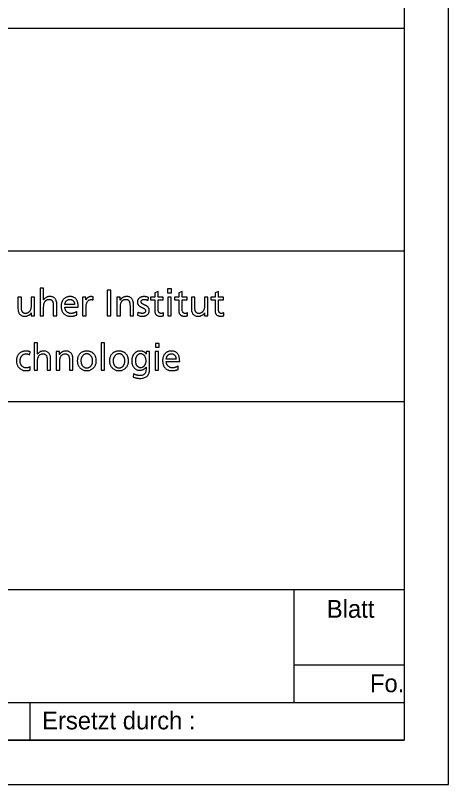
# Model space of a CAD drawing. Extents: x 0 to 420, y 0 to 297.
# Drawn here: x 396.16 to 420.5, y 0 to 43.24 of the extents above; entities that cross this region are included whole.
import ezdxf

# ---------------------------------------------------------------- set-up
doc = ezdxf.new("R2010")
doc.units = 0
doc.layers.add('90_Plankopf', color=7, linetype='Continuous')

msp = doc.modelspace()

# ---------------------------------------------------------------- linework, layer by layer
at = {"layer": '90_Plankopf'}
for p, q in [((418, 42.495), (329.06, 42.495)), ((418, 42.495), (418, 2.5)), ((329.06, 29.995), (418, 29.995)), ((329.06, 29.995), (418, 29.995)), ((418, 29.995), (418, 2.5)), ((400.528, 27.242), (400.528, 27.416)), ((403.616, 27.22), (403.633, 27.389)), ((399.486, 26.98), (398.941, 26.98)), ((398.941, 26.836), (399.693, 26.836)), ((399.612, 26.396), (399.612, 26.59)), ((403.036, 26.559), (403.026, 26.386)), ((404.481, 26.357), (404.481, 26.522)), ((405.833, 26.357), (405.833, 26.522)), ((407.872, 26.357), (407.872, 26.522)), ((396.976, 24.168), (396.992, 24.329)), ((405.186, 23.92), (404.642, 23.92)), ((397, 23.312), (396.986, 23.485)), ((404.642, 23.776), (405.393, 23.776)), ((405.312, 23.337), (405.312, 23.53)), ((402.798, 23.087), (402.777, 22.907)), ((376.001, 21.535), (418, 21.535)), ((376.001, 10.96), (418, 10.96)), ((411.824, 4.615), (411.824, 10.96)), ((411.824, 6.73), (418, 6.73)), ((376.001, 4.615), (418, 4.615)), ((397.001, 2.5), (397.001, 4.615)), ((418, 2.5), (329.06, 2.5)), ((334.9, 2.5), (418, 2.5)), ((334.9, 2.5), (418, 2.5))]:
    msp.add_line(p, q, dxfattribs=at)
for points in [[(0, 0), (420.5, 0), (420.5, 297), (0, 297)], [(12.5, 294.5), (418, 294.5), (418, 2.5), (12.5, 2.5)]]:
    msp.add_lwpolyline(points, close=True, dxfattribs=at)
for points in [[(397.755, 27.255), (397.751, 27.255), (397.751, 27.9), (397.557, 27.9), (397.557, 26.353), (397.751, 26.353), (397.751, 26.84)], [(401.323, 26.353), (401.529, 26.353), (401.529, 27.793), (401.323, 27.793), (401.323, 26.353)], [(404.186, 26.673), (404.186, 27.248), (404.464, 27.248), (404.464, 27.405), (404.186, 27.405), (404.186, 27.711), (403.992, 27.649), (403.992, 27.405), (403.754, 27.405), (403.754, 27.248), (403.992, 27.248), (403.992, 26.633)], [(404.927, 27.64), (404.927, 27.859), (404.708, 27.859), (404.708, 27.64), (404.927, 27.64)], [(405.538, 26.673), (405.538, 27.248), (405.816, 27.248), (405.816, 27.405), (405.538, 27.405), (405.538, 27.711), (405.344, 27.649), (405.344, 27.405), (405.106, 27.405), (405.106, 27.248), (405.344, 27.248), (405.344, 26.633)], [(407.577, 26.673), (407.577, 27.248), (407.855, 27.248), (407.855, 27.405), (407.577, 27.405), (407.577, 27.711), (407.383, 27.649), (407.383, 27.405), (407.146, 27.405), (407.146, 27.248), (407.383, 27.248), (407.383, 26.633)], [(396.502, 26.86), (396.502, 27.405), (396.308, 27.405), (396.308, 26.78)], [(397.047, 26.52), (397.051, 26.52), (397.051, 26.353), (397.239, 26.353), (397.239, 27.405), (397.045, 27.405), (397.045, 26.918)], [(400.126, 27.242), (400.122, 27.242), (400.122, 27.405), (399.94, 27.405), (399.94, 26.353), (400.134, 26.353), (400.134, 26.832)], [(402.058, 27.238), (402.054, 27.238), (402.054, 27.405), (401.866, 27.405), (401.866, 26.353), (402.06, 26.353), (402.06, 26.84)], [(404.72, 27.405), (404.72, 26.353), (404.914, 26.353), (404.914, 27.405), (404.72, 27.405)], [(406.242, 26.86), (406.242, 27.405), (406.048, 27.405), (406.048, 26.78)], [(406.786, 26.52), (406.79, 26.52), (406.79, 26.353), (406.978, 26.353), (406.978, 27.405), (406.784, 27.405), (406.784, 26.918)], [(398.293, 26.898), (398.293, 26.353), (398.487, 26.353), (398.487, 26.978)], [(402.603, 26.898), (402.603, 26.353), (402.797, 26.353), (402.797, 26.978)], [(397.409, 24.195), (397.405, 24.195), (397.405, 24.841), (397.211, 24.841), (397.211, 23.293), (397.405, 23.293), (397.405, 23.78)], [(400.982, 23.293), (401.176, 23.293), (401.176, 24.841), (400.982, 24.841), (400.982, 23.293)], [(404.247, 24.581), (404.247, 24.799), (404.028, 24.799), (404.028, 24.581), (404.247, 24.581)], [(398.652, 24.178), (398.647, 24.178), (398.647, 24.346), (398.46, 24.346), (398.46, 23.293), (398.654, 23.293), (398.654, 23.78)], [(403.698, 23.339), (403.698, 24.346), (403.518, 24.346), (403.518, 24.189), (403.514, 24.189)], [(404.015, 24.346), (404.015, 23.293), (404.209, 23.293), (404.209, 24.346), (404.015, 24.346)], [(397.948, 23.838), (397.948, 23.293), (398.142, 23.293), (398.142, 23.918)], [(399.196, 23.838), (399.196, 23.293), (399.39, 23.293), (399.39, 23.918)], [(403.5, 23.456), (403.504, 23.456), (403.504, 23.353)]]:
    msp.add_lwpolyline(points, dxfattribs=at)
for points in [[(397.751, 26.84), (397.751, 26.904), (397.757, 26.963), (397.77, 27.016), (397.782, 27.069), (397.802, 27.114), (397.828, 27.152), (397.854, 27.191), (397.887, 27.221), (397.927, 27.242), (397.968, 27.262), (398.015, 27.273), (398.071, 27.273), (398.127, 27.27), (398.171, 27.254), (398.204, 27.226), (398.236, 27.198), (398.259, 27.156), (398.273, 27.102), (398.287, 27.048), (398.294, 26.979), (398.293, 26.898)], [(398.487, 26.978), (398.488, 27.073), (398.474, 27.154), (398.446, 27.221), (398.418, 27.288), (398.374, 27.34), (398.316, 27.376), (398.258, 27.412), (398.184, 27.43), (398.093, 27.43), (398.019, 27.43), (397.954, 27.414), (397.895, 27.384), (397.837, 27.354), (397.791, 27.311), (397.755, 27.255)], [(399.693, 26.836), (399.693, 26.921), (399.685, 26.999), (399.67, 27.071), (399.654, 27.143), (399.628, 27.206), (399.592, 27.26), (399.556, 27.313), (399.509, 27.355), (399.449, 27.385), (399.389, 27.414), (399.316, 27.43), (399.228, 27.43), (399.154, 27.43), (399.086, 27.416), (399.026, 27.391), (398.966, 27.365), (398.914, 27.328), (398.87, 27.281), (398.827, 27.233), (398.794, 27.177), (398.771, 27.112), (398.747, 27.048), (398.736, 26.976), (398.735, 26.898), (398.735, 26.812), (398.746, 26.734), (398.768, 26.664), (398.789, 26.594), (398.823, 26.534), (398.868, 26.485), (398.912, 26.434), (398.969, 26.396), (399.037, 26.369), (399.106, 26.342), (399.187, 26.328), (399.28, 26.328), (399.337, 26.328), (399.386, 26.332), (399.427, 26.34), (399.467, 26.347), (399.502, 26.356), (399.532, 26.367), (399.561, 26.377), (399.588, 26.387), (399.612, 26.396)], [(398.941, 26.98), (398.945, 27.015), (398.953, 27.049), (398.965, 27.083), (398.977, 27.118), (398.994, 27.149), (399.017, 27.178), (399.04, 27.206), (399.068, 27.229), (399.102, 27.247), (399.136, 27.264), (399.177, 27.273), (399.224, 27.273), (399.266, 27.273), (399.303, 27.265), (399.336, 27.25), (399.368, 27.235), (399.395, 27.214), (399.418, 27.187), (399.44, 27.16), (399.457, 27.129), (399.469, 27.094), (399.48, 27.059), (399.486, 27.021), (399.486, 26.98)], [(400.528, 27.416), (400.515, 27.418), (400.502, 27.421), (400.49, 27.423), (400.478, 27.425), (400.464, 27.427), (400.45, 27.428), (400.436, 27.429), (400.419, 27.43), (400.401, 27.43), (400.363, 27.43), (400.327, 27.422), (400.291, 27.406), (400.256, 27.39), (400.224, 27.368), (400.196, 27.339), (400.167, 27.311), (400.144, 27.279), (400.126, 27.242)], [(400.134, 26.832), (400.135, 26.92), (400.147, 26.996), (400.17, 27.06), (400.194, 27.124), (400.227, 27.174), (400.27, 27.208), (400.312, 27.243), (400.363, 27.26), (400.421, 27.261), (400.438, 27.261), (400.456, 27.26), (400.474, 27.257), (400.493, 27.254), (400.511, 27.249), (400.528, 27.242)], [(402.797, 26.978), (402.797, 27.073), (402.783, 27.154), (402.755, 27.221), (402.727, 27.288), (402.684, 27.34), (402.626, 27.376), (402.568, 27.412), (402.493, 27.43), (402.402, 27.43), (402.353, 27.43), (402.306, 27.422), (402.261, 27.407), (402.216, 27.392), (402.176, 27.37), (402.14, 27.341), (402.105, 27.312), (402.077, 27.278), (402.058, 27.238)], [(402.06, 26.84), (402.06, 26.904), (402.066, 26.963), (402.079, 27.016), (402.092, 27.069), (402.111, 27.114), (402.137, 27.152), (402.163, 27.191), (402.196, 27.221), (402.237, 27.242), (402.277, 27.262), (402.325, 27.273), (402.38, 27.273), (402.436, 27.27), (402.48, 27.254), (402.513, 27.226), (402.546, 27.198), (402.569, 27.156), (402.582, 27.102), (402.597, 27.048), (402.603, 26.979), (402.603, 26.898)], [(403.633, 27.389), (403.595, 27.4), (403.556, 27.41), (403.517, 27.418), (403.478, 27.426), (403.436, 27.43), (403.391, 27.43), (403.339, 27.43), (403.29, 27.423), (403.245, 27.41), (403.2, 27.397), (403.161, 27.377), (403.127, 27.35), (403.094, 27.323), (403.067, 27.29), (403.049, 27.249), (403.03, 27.208), (403.02, 27.161), (403.02, 27.106), (403.02, 27.064), (403.029, 27.028), (403.045, 26.997), (403.061, 26.966), (403.083, 26.94), (403.11, 26.917), (403.137, 26.895), (403.167, 26.875), (403.199, 26.857), (403.232, 26.84), (403.264, 26.824), (403.296, 26.809), (403.329, 26.793), (403.358, 26.777), (403.385, 26.761), (403.412, 26.745), (403.434, 26.727), (403.451, 26.706), (403.467, 26.686), (403.475, 26.663), (403.476, 26.636), (403.475, 26.607), (403.469, 26.584), (403.457, 26.564), (403.445, 26.545), (403.43, 26.529), (403.41, 26.518), (403.39, 26.506), (403.369, 26.498), (403.346, 26.493), (403.323, 26.487), (403.3, 26.485), (403.278, 26.485), (403.258, 26.485), (403.235, 26.488), (403.207, 26.493), (403.179, 26.499), (403.15, 26.507), (403.12, 26.518), (403.09, 26.529), (403.062, 26.543), (403.036, 26.559)], [(403.026, 26.386), (403.071, 26.363), (403.117, 26.347), (403.167, 26.339), (403.215, 26.331), (403.265, 26.327), (403.315, 26.328), (403.362, 26.328), (403.408, 26.335), (403.451, 26.348), (403.495, 26.361), (403.534, 26.381), (403.569, 26.408), (403.603, 26.435), (403.631, 26.469), (403.651, 26.51), (403.671, 26.551), (403.682, 26.6), (403.682, 26.656), (403.682, 26.704), (403.673, 26.745), (403.657, 26.778), (403.64, 26.811), (403.619, 26.84), (403.592, 26.863), (403.565, 26.886), (403.535, 26.906), (403.503, 26.922), (403.47, 26.939), (403.438, 26.954), (403.406, 26.968), (403.373, 26.983), (403.343, 26.998), (403.317, 27.013), (403.289, 27.029), (403.268, 27.047), (403.251, 27.068), (403.235, 27.089), (403.226, 27.115), (403.226, 27.145), (403.226, 27.174), (403.235, 27.198), (403.252, 27.217), (403.269, 27.236), (403.292, 27.25), (403.32, 27.259), (403.347, 27.269), (403.378, 27.273), (403.412, 27.273), (403.423, 27.273), (403.439, 27.271), (403.457, 27.269), (403.475, 27.266), (403.494, 27.261), (403.515, 27.256), (403.535, 27.251), (403.554, 27.246), (403.572, 27.239), (403.59, 27.233), (403.605, 27.226), (403.616, 27.22)], [(397.045, 26.918), (397.045, 26.854), (397.039, 26.795), (397.026, 26.742), (397.013, 26.69), (396.994, 26.644), (396.968, 26.606), (396.941, 26.567), (396.908, 26.538), (396.868, 26.517), (396.828, 26.496), (396.78, 26.485), (396.725, 26.485), (396.669, 26.488), (396.624, 26.504), (396.592, 26.532), (396.559, 26.561), (396.536, 26.602), (396.522, 26.656), (396.508, 26.71), (396.502, 26.779), (396.502, 26.86)], [(399.612, 26.59), (399.6, 26.58), (399.583, 26.569), (399.559, 26.557), (399.536, 26.545), (399.51, 26.534), (399.48, 26.523), (399.45, 26.512), (399.419, 26.503), (399.386, 26.496), (399.353, 26.489), (399.32, 26.485), (399.288, 26.485), (399.242, 26.485), (399.198, 26.493), (399.156, 26.51), (399.115, 26.527), (399.078, 26.551), (399.046, 26.582), (399.014, 26.613), (398.988, 26.65), (398.97, 26.693), (398.951, 26.736), (398.942, 26.783), (398.941, 26.836)], [(406.784, 26.918), (406.784, 26.854), (406.778, 26.795), (406.765, 26.742), (406.753, 26.69), (406.733, 26.644), (406.707, 26.606), (406.681, 26.567), (406.648, 26.538), (406.607, 26.517), (406.567, 26.496), (406.519, 26.485), (406.464, 26.485), (406.408, 26.488), (406.364, 26.504), (406.331, 26.532), (406.299, 26.561), (406.276, 26.602), (406.262, 26.656), (406.248, 26.71), (406.241, 26.779), (406.242, 26.86)], [(396.308, 26.78), (396.308, 26.685), (396.322, 26.605), (396.35, 26.537), (396.378, 26.47), (396.421, 26.418), (396.479, 26.382), (396.537, 26.347), (396.612, 26.328), (396.702, 26.328), (396.751, 26.328), (396.799, 26.336), (396.844, 26.351), (396.889, 26.367), (396.929, 26.389), (396.964, 26.417), (397, 26.446), (397.027, 26.48), (397.047, 26.52)], [(403.992, 26.633), (403.992, 26.563), (404.005, 26.506), (404.031, 26.461), (404.057, 26.416), (404.095, 26.382), (404.143, 26.36), (404.191, 26.339), (404.249, 26.328), (404.316, 26.328), (404.347, 26.328), (404.377, 26.332), (404.405, 26.338), (404.434, 26.344), (404.459, 26.35), (404.481, 26.357)], [(404.481, 26.522), (404.466, 26.513), (404.448, 26.504), (404.426, 26.497), (404.404, 26.489), (404.379, 26.485), (404.349, 26.485), (404.319, 26.485), (404.292, 26.492), (404.267, 26.507), (404.243, 26.521), (404.223, 26.542), (404.208, 26.57), (404.194, 26.598), (404.186, 26.632), (404.186, 26.673)], [(405.344, 26.633), (405.344, 26.563), (405.357, 26.506), (405.383, 26.461), (405.409, 26.416), (405.447, 26.382), (405.495, 26.36), (405.543, 26.339), (405.601, 26.328), (405.668, 26.328), (405.699, 26.328), (405.729, 26.332), (405.757, 26.338), (405.786, 26.344), (405.811, 26.35), (405.833, 26.357)], [(405.833, 26.522), (405.818, 26.513), (405.8, 26.504), (405.778, 26.497), (405.756, 26.489), (405.731, 26.485), (405.701, 26.485), (405.671, 26.485), (405.644, 26.492), (405.619, 26.507), (405.595, 26.521), (405.575, 26.542), (405.56, 26.57), (405.546, 26.598), (405.538, 26.632), (405.538, 26.673)], [(406.048, 26.78), (406.048, 26.685), (406.061, 26.605), (406.089, 26.537), (406.117, 26.47), (406.16, 26.418), (406.219, 26.382), (406.277, 26.347), (406.351, 26.328), (406.442, 26.328), (406.491, 26.328), (406.538, 26.336), (406.583, 26.351), (406.628, 26.367), (406.669, 26.389), (406.704, 26.417), (406.739, 26.446), (406.767, 26.48), (406.786, 26.52)], [(407.383, 26.633), (407.383, 26.563), (407.396, 26.506), (407.422, 26.461), (407.449, 26.416), (407.486, 26.382), (407.534, 26.36), (407.582, 26.339), (407.64, 26.328), (407.707, 26.328), (407.738, 26.328), (407.768, 26.332), (407.796, 26.338), (407.825, 26.344), (407.85, 26.35), (407.872, 26.357)], [(407.872, 26.522), (407.857, 26.513), (407.839, 26.504), (407.818, 26.497), (407.796, 26.489), (407.77, 26.485), (407.74, 26.485), (407.71, 26.485), (407.683, 26.492), (407.658, 26.507), (407.634, 26.521), (407.614, 26.542), (407.6, 26.57), (407.585, 26.598), (407.577, 26.632), (407.577, 26.673)], [(396.992, 24.329), (396.973, 24.337), (396.951, 24.343), (396.924, 24.35), (396.897, 24.356), (396.869, 24.361), (396.84, 24.365), (396.811, 24.368), (396.783, 24.37), (396.757, 24.37), (396.676, 24.37), (396.603, 24.356), (396.537, 24.329), (396.472, 24.302), (396.415, 24.264), (396.368, 24.215), (396.321, 24.166), (396.284, 24.108), (396.259, 24.041), (396.234, 23.973), (396.221, 23.9), (396.22, 23.819), (396.221, 23.744), (396.234, 23.673), (396.26, 23.606), (396.285, 23.54), (396.322, 23.482), (396.37, 23.431), (396.417, 23.381), (396.474, 23.341), (396.539, 23.312), (396.605, 23.284), (396.677, 23.269), (396.757, 23.268), (396.781, 23.268), (396.806, 23.269), (396.833, 23.272), (396.861, 23.274), (396.889, 23.278), (396.917, 23.284), (396.946, 23.29), (396.973, 23.299), (397, 23.312)], [(396.986, 23.485), (396.966, 23.472), (396.944, 23.461), (396.92, 23.452), (396.896, 23.443), (396.872, 23.437), (396.848, 23.432), (396.823, 23.428), (396.8, 23.425), (396.777, 23.425), (396.728, 23.426), (396.684, 23.433), (396.645, 23.448), (396.607, 23.463), (396.574, 23.484), (396.546, 23.51), (396.518, 23.536), (396.496, 23.566), (396.478, 23.6), (396.461, 23.633), (396.448, 23.669), (396.439, 23.706), (396.431, 23.744), (396.427, 23.782), (396.427, 23.819), (396.427, 23.87), (396.434, 23.919), (396.449, 23.965), (396.464, 24.012), (396.486, 24.054), (396.515, 24.091), (396.544, 24.129), (396.579, 24.158), (396.621, 24.18), (396.663, 24.202), (396.711, 24.213), (396.765, 24.213), (396.797, 24.213), (396.83, 24.21), (396.866, 24.202), (396.902, 24.195), (396.938, 24.184), (396.976, 24.168)], [(397.405, 23.78), (397.405, 23.845), (397.411, 23.903), (397.424, 23.956), (397.437, 24.009), (397.456, 24.054), (397.482, 24.093), (397.508, 24.131), (397.542, 24.161), (397.582, 24.182), (397.622, 24.203), (397.67, 24.213), (397.725, 24.213), (397.781, 24.21), (397.825, 24.195), (397.858, 24.166), (397.891, 24.138), (397.914, 24.097), (397.928, 24.042), (397.942, 23.988), (397.948, 23.92), (397.948, 23.838)], [(398.142, 23.918), (398.142, 24.013), (398.128, 24.094), (398.1, 24.161), (398.072, 24.229), (398.029, 24.28), (397.971, 24.316), (397.913, 24.352), (397.838, 24.37), (397.748, 24.37), (397.674, 24.37), (397.608, 24.355), (397.55, 24.325), (397.492, 24.294), (397.445, 24.251), (397.409, 24.195)], [(399.39, 23.918), (399.391, 24.013), (399.377, 24.094), (399.349, 24.161), (399.321, 24.229), (399.277, 24.28), (399.219, 24.316), (399.161, 24.352), (399.087, 24.37), (398.996, 24.37), (398.947, 24.37), (398.9, 24.362), (398.855, 24.347), (398.81, 24.332), (398.769, 24.31), (398.734, 24.281), (398.699, 24.253), (398.671, 24.219), (398.652, 24.178)], [(398.654, 23.78), (398.654, 23.845), (398.66, 23.903), (398.673, 23.956), (398.685, 24.009), (398.705, 24.054), (398.731, 24.093), (398.757, 24.131), (398.79, 24.161), (398.83, 24.182), (398.871, 24.203), (398.918, 24.213), (398.974, 24.213), (399.03, 24.21), (399.074, 24.195), (399.107, 24.166), (399.139, 24.138), (399.162, 24.097), (399.176, 24.042), (399.19, 23.988), (399.197, 23.92), (399.196, 23.838)], [(400.697, 23.945), (400.691, 23.978), (400.682, 24.01), (400.671, 24.041), (400.645, 24.108), (400.609, 24.166), (400.562, 24.215), (400.515, 24.264), (400.458, 24.302), (400.393, 24.329), (400.328, 24.356), (400.255, 24.37), (400.175, 24.37), (400.094, 24.37), (400.021, 24.356), (399.955, 24.329), (399.889, 24.302), (399.833, 24.264), (399.786, 24.215), (399.739, 24.166), (399.702, 24.108), (399.677, 24.041), (399.651, 23.973), (399.639, 23.9), (399.638, 23.819)], [(399.844, 23.819), (399.844, 23.87), (399.852, 23.919), (399.867, 23.965), (399.882, 24.012), (399.903, 24.054), (399.932, 24.091), (399.96, 24.129), (399.994, 24.158), (400.035, 24.18), (400.076, 24.202), (400.122, 24.213), (400.175, 24.213), (400.226, 24.213), (400.272, 24.202), (400.313, 24.18), (400.353, 24.158), (400.388, 24.129), (400.416, 24.091), (400.444, 24.054), (400.466, 24.012), (400.48, 23.965), (400.495, 23.919), (400.503, 23.87), (400.503, 23.819), (400.503, 23.782), (400.499, 23.744), (400.49, 23.706), (400.482, 23.669), (400.47, 23.633), (400.452, 23.6), (400.436, 23.566), (400.414, 23.536), (400.388, 23.51), (400.362, 23.484), (400.332, 23.463), (400.296, 23.448), (400.261, 23.433), (400.22, 23.426), (400.175, 23.425), (400.129, 23.426), (400.088, 23.433), (400.052, 23.448), (400.017, 23.463), (399.986, 23.484), (399.959, 23.51), (399.933, 23.536), (399.912, 23.566), (399.895, 23.6), (399.878, 23.633), (399.865, 23.669), (399.857, 23.706), (399.849, 23.744), (399.844, 23.782), (399.844, 23.819)], [(402.507, 23.945), (402.501, 23.978), (402.492, 24.01), (402.481, 24.041), (402.455, 24.108), (402.419, 24.166), (402.372, 24.215), (402.325, 24.264), (402.268, 24.302), (402.203, 24.329), (402.138, 24.356), (402.065, 24.37), (401.985, 24.37), (401.904, 24.37), (401.831, 24.356), (401.765, 24.329), (401.699, 24.302), (401.643, 24.264), (401.596, 24.215), (401.549, 24.166), (401.512, 24.108), (401.487, 24.041), (401.461, 23.973), (401.449, 23.9), (401.448, 23.819)], [(401.655, 23.819), (401.655, 23.87), (401.662, 23.919), (401.677, 23.965), (401.692, 24.012), (401.713, 24.054), (401.742, 24.091), (401.77, 24.129), (401.805, 24.158), (401.845, 24.18), (401.886, 24.202), (401.932, 24.213), (401.985, 24.213), (402.036, 24.213), (402.082, 24.202), (402.123, 24.18), (402.163, 24.158), (402.198, 24.129), (402.226, 24.091), (402.254, 24.054), (402.276, 24.012), (402.29, 23.965), (402.305, 23.919), (402.313, 23.87), (402.313, 23.819), (402.313, 23.782), (402.309, 23.744), (402.3, 23.706), (402.292, 23.669), (402.28, 23.633), (402.263, 23.6), (402.246, 23.566), (402.224, 23.536), (402.198, 23.51), (402.172, 23.484), (402.142, 23.463), (402.106, 23.448), (402.071, 23.433), (402.03, 23.426), (401.985, 23.425), (401.939, 23.426), (401.898, 23.433), (401.862, 23.448), (401.827, 23.463), (401.796, 23.484), (401.769, 23.51), (401.743, 23.536), (401.722, 23.566), (401.705, 23.6), (401.688, 23.633), (401.675, 23.669), (401.667, 23.706), (401.659, 23.744), (401.655, 23.782), (401.655, 23.819)], [(403.514, 24.189), (403.495, 24.227), (403.47, 24.259), (403.44, 24.286), (403.409, 24.313), (403.371, 24.334), (403.327, 24.348), (403.282, 24.363), (403.229, 24.37), (403.167, 24.37), (403.104, 24.37), (403.047, 24.359), (402.996, 24.338), (402.946, 24.317), (402.902, 24.288), (402.864, 24.251), (402.827, 24.215), (402.796, 24.172), (402.771, 24.125), (402.746, 24.077), (402.727, 24.027), (402.715, 23.973), (402.703, 23.919), (402.697, 23.866), (402.697, 23.811), (402.697, 23.742), (402.706, 23.677), (402.725, 23.615), (402.743, 23.554), (402.772, 23.498), (402.809, 23.45), (402.846, 23.402), (402.893, 23.364), (402.949, 23.336), (403.006, 23.308), (403.071, 23.294), (403.147, 23.293), (403.192, 23.293), (403.236, 23.299), (403.279, 23.311), (403.323, 23.323), (403.363, 23.341), (403.401, 23.365), (403.439, 23.39), (403.472, 23.42), (403.5, 23.456)], [(403.196, 23.45), (403.151, 23.45), (403.11, 23.46), (403.074, 23.48), (403.038, 23.5), (403.007, 23.527), (402.982, 23.561), (402.956, 23.596), (402.937, 23.635), (402.923, 23.68), (402.91, 23.724), (402.903, 23.772), (402.903, 23.821), (402.903, 23.857), (402.907, 23.894), (402.915, 23.931), (402.922, 23.968), (402.934, 24.003), (402.95, 24.037), (402.965, 24.071), (402.985, 24.101), (403.008, 24.127), (403.032, 24.154), (403.059, 24.175), (403.091, 24.19), (403.122, 24.205), (403.157, 24.213), (403.196, 24.213), (403.248, 24.213), (403.293, 24.202), (403.331, 24.181), (403.37, 24.16), (403.402, 24.13), (403.427, 24.092), (403.453, 24.055), (403.472, 24.012), (403.485, 23.963), (403.497, 23.914), (403.504, 23.862), (403.504, 23.807), (403.504, 23.758), (403.496, 23.711), (403.481, 23.668), (403.466, 23.625), (403.445, 23.587), (403.418, 23.555), (403.391, 23.522), (403.359, 23.497), (403.321, 23.478), (403.283, 23.46), (403.242, 23.45), (403.196, 23.45)], [(405.393, 23.776), (405.393, 23.861), (405.385, 23.94), (405.37, 24.012), (405.354, 24.084), (405.328, 24.146), (405.292, 24.2), (405.256, 24.254), (405.209, 24.295), (405.149, 24.325), (405.089, 24.355), (405.016, 24.37), (404.928, 24.37), (404.854, 24.37), (404.786, 24.357), (404.726, 24.331), (404.666, 24.305), (404.614, 24.269), (404.57, 24.221), (404.527, 24.174), (404.494, 24.118), (404.471, 24.052), (404.447, 23.988), (404.436, 23.916), (404.435, 23.838), (404.435, 23.752), (404.446, 23.674), (404.468, 23.604), (404.49, 23.535), (404.523, 23.475), (404.568, 23.425), (404.612, 23.375), (404.669, 23.336), (404.737, 23.309), (404.806, 23.282), (404.887, 23.269), (404.98, 23.268), (405.037, 23.269), (405.086, 23.273), (405.127, 23.28), (405.167, 23.288), (405.202, 23.297), (405.232, 23.307), (405.261, 23.317), (405.288, 23.327), (405.312, 23.337)], [(404.642, 23.92), (404.645, 23.955), (404.653, 23.989), (404.665, 24.024), (404.677, 24.058), (404.695, 24.089), (404.717, 24.118), (404.74, 24.147), (404.768, 24.17), (404.802, 24.187), (404.836, 24.204), (404.877, 24.213), (404.924, 24.213), (404.966, 24.213), (405.003, 24.206), (405.036, 24.19), (405.068, 24.175), (405.096, 24.154), (405.118, 24.127), (405.14, 24.101), (405.157, 24.069), (405.169, 24.034), (405.18, 23.999), (405.186, 23.961), (405.186, 23.92)], [(399.638, 23.819), (399.639, 23.744), (399.652, 23.673), (399.677, 23.606), (399.703, 23.54), (399.74, 23.482), (399.787, 23.431), (399.835, 23.381), (399.891, 23.341), (399.957, 23.312), (400.022, 23.284), (400.095, 23.269), (400.175, 23.268), (400.254, 23.269), (400.326, 23.284), (400.391, 23.312), (400.457, 23.341), (400.513, 23.381), (400.56, 23.431), (400.608, 23.482), (400.644, 23.54), (400.67, 23.606), (400.696, 23.673), (400.709, 23.744), (400.709, 23.819), (400.709, 23.863), (400.705, 23.905), (400.697, 23.945)], [(401.448, 23.819), (401.449, 23.744), (401.462, 23.673), (401.487, 23.606), (401.513, 23.54), (401.55, 23.482), (401.597, 23.431), (401.645, 23.381), (401.701, 23.341), (401.767, 23.312), (401.832, 23.284), (401.905, 23.269), (401.985, 23.268), (402.064, 23.269), (402.136, 23.284), (402.201, 23.312), (402.267, 23.341), (402.323, 23.381), (402.37, 23.431), (402.418, 23.482), (402.454, 23.54), (402.48, 23.606), (402.506, 23.673), (402.519, 23.744), (402.519, 23.819), (402.519, 23.863), (402.515, 23.905), (402.507, 23.945)], [(403.504, 23.353), (403.503, 23.279), (403.491, 23.214), (403.465, 23.16), (403.439, 23.106), (403.402, 23.065), (403.353, 23.036), (403.304, 23.007), (403.246, 22.992), (403.178, 22.992), (403.142, 22.992), (403.11, 22.994), (403.079, 22.997), (403.049, 23), (403.019, 23.006), (402.99, 23.014), (402.961, 23.021), (402.931, 23.031), (402.9, 23.043), (402.869, 23.055), (402.835, 23.07), (402.798, 23.087)], [(405.312, 23.53), (405.3, 23.521), (405.283, 23.51), (405.26, 23.497), (405.237, 23.485), (405.21, 23.474), (405.18, 23.463), (405.151, 23.452), (405.119, 23.443), (405.086, 23.436), (405.053, 23.429), (405.021, 23.426), (404.988, 23.425), (404.942, 23.426), (404.898, 23.434), (404.857, 23.451), (404.815, 23.468), (404.778, 23.492), (404.746, 23.523), (404.714, 23.554), (404.688, 23.59), (404.67, 23.633), (404.652, 23.676), (404.642, 23.724), (404.642, 23.776)], [(402.777, 22.907), (402.833, 22.888), (402.883, 22.873), (402.926, 22.863), (402.968, 22.852), (403.008, 22.845), (403.045, 22.841), (403.082, 22.837), (403.118, 22.835), (403.155, 22.835), (403.28, 22.835), (403.383, 22.855), (403.463, 22.895), (403.544, 22.934), (403.603, 22.991), (403.641, 23.066), (403.679, 23.141), (403.698, 23.232), (403.698, 23.339)]]:
    msp.add_open_spline(points, degree=3, dxfattribs=at)

# ---------------------------------------------------------------- texts
for s, p in [('Blatt', (413.657, 9.379)), ('Fo.', (416.08, 5.196)), ('Ersetzt durch :', (397.663, 3.105))]:
    msp.add_text(s, height=1, dxfattribs=at).set_placement(p)

doc.saveas('drawing.dxf')
